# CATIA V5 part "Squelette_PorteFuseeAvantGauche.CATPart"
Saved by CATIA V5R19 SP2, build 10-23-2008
Part number: Squelette_PorteFuseeAvantGauche
Bounding box of the stored display mesh (mm): x -33.824 to 7.506, y -233.644 to -186.535, z 121.676 to 160.612
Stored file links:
  D:\Mes Documents\ressource\CATIA\Ensemble Catia\Voiture_Telecommmande\SchemaCinematiqueFinal\Squelette_PorteFuseeAvantGauche.CATPart
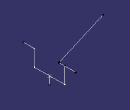
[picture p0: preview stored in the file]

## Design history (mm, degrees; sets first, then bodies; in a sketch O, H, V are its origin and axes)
AxisSystem1: origin (0, 0, 0), X (1, 0, 0), Y (0, 1, 0), Z (0, 0, 1)
Set1
  Point1 to Point11: stored without definition
  Line1 to Line3: stored without definition
  Plane1: stored without definition
  Sketch1 on Plane1, origin (1.5118, 0.0225, -0.0264), H (-0.0149, 0.9999, 0), V (0.0174, 0.0003, 0.9998)
    line L1 (-233.7304, 143.9301) -> (-224.1181, 143.9301)
    point P1 (-233.7304, 143.9301)
    line L2 (-224.1181, 143.9301) -> (-224.1181, 128.7204)
    line L3 (-224.1181, 128.7204) -> (-196.496, 128.7204)
    line L4 (-196.496, 128.7204) -> (-196.496, 143.5095)
    line L5 (-196.496, 143.5095) -> (-186.6158, 143.5095)
    point P6 (-186.6158, 143.5095)
    reference projected point E1 (-186.6158, 143.5095) from Point3
    reference projected point E2 (-233.7304, 143.9301) from Point9
    projected point E3 (-210.307, 128.7204) from Point12
    line L6 (-196.496, 143.5095) -> (-201.6467, 143.5095)
    horizontal: L1 H, L3 H, L5 H, L6 H
    vertical: L2 V, L4 V
    coincidence: P6 E1, P1 E2
    midpoint: E3 L3
  Point12 "Centre": stored without definition
Body1 (main body)
Body2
